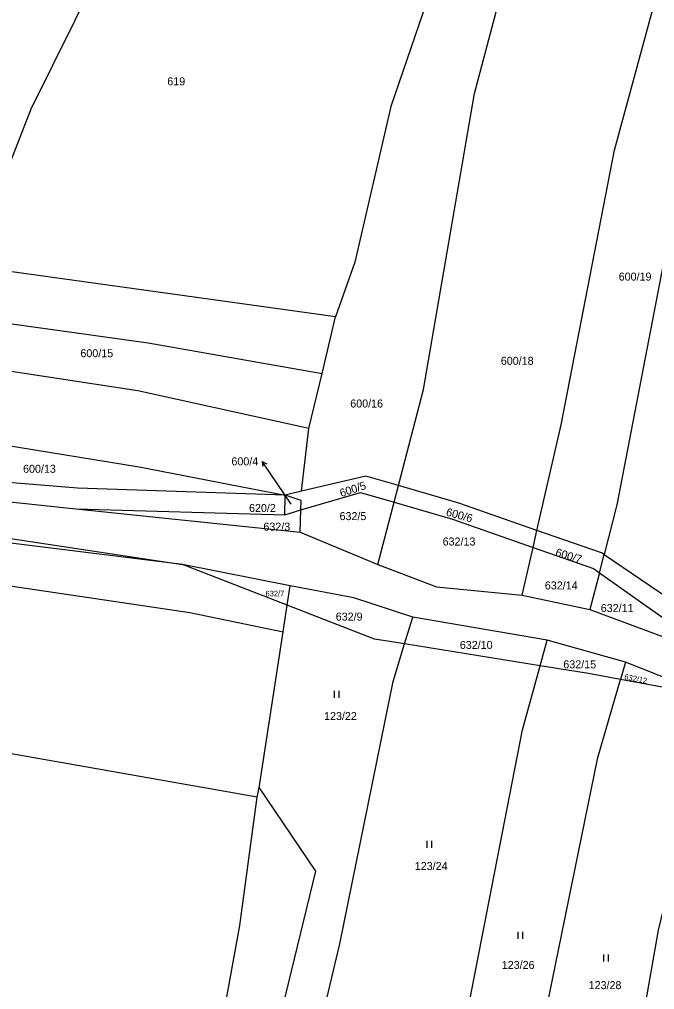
# Model space of a CAD drawing. Extents: x -744566 to -741843, y -1128407 to -1126744.
# Drawn here: x -742633.6 to -742498.8, y -1127345.9 to -1127139.9 of the extents above; entities that cross this region are included whole.
import ezdxf

# ---------------------------------------------------------------- set-up
doc = ezdxf.new("R2010")
doc.units = 0
for name, color, linetype in [('Hranice parcel', 7, 'Continuous'), ('Parcelní čísla', 7, 'Continuous'), ('Pop  PČ popisy', 7, 'Continuous'), ('Značky kultur', 7, 'Continuous')]:
    doc.layers.add(name, color=color, linetype=linetype)

msp = doc.modelspace()

# ---------------------------------------------------------------- linework, layer by layer
at = {"layer": 'Hranice parcel'}
for p, q in [((-742566.48, -1127203.04), (-742644.1, -1127192.22)), ((-742569.32, -1127215.09), (-742566.48, -1127203.04)), ((-742572.17, -1127226.73), (-742569.32, -1127215.09)), ((-742573.72, -1127240.07), (-742572.17, -1127226.73)), ((-742573.72, -1127240.07), (-742577.19, -1127240.89)), ((-742554.07, -1127242.4), (-742553.15, -1127238.87)), ((-742639.2, -1127241.9), (-742621.56, -1127243.8)), ((-742577.26, -1127245.05), (-742577.19, -1127240.89)), ((-742557.53, -1127255.65), (-742554.07, -1127242.4)), ((-742678.76, -1127243.56), (-742598.97, -1127255.65)), ((-742621.56, -1127243.8), (-742574.02, -1127248.78)), ((-742621.56, -1127243.8), (-742577.26, -1127245.05)), ((-742577.26, -1127245.05), (-742573.86, -1127244.05)), ((-742574.02, -1127248.78), (-742573.86, -1127244.05)), ((-742574.02, -1127248.78), (-742557.53, -1127255.65)), ((-742524.58, -1127252.01), (-742523.75, -1127248.38)), ((-742526.9, -1127262.12), (-742524.58, -1127252.01)), ((-742510.5, -1127257.39), (-742509.51, -1127253.53)), ((-742509.51, -1127253.53), (-742483.68, -1127270.99)), ((-742576.08, -1127260.13), (-742598.97, -1127255.65)), ((-742576.72, -1127264.27), (-742598.97, -1127255.65)), ((-742510.5, -1127257.39), (-742512.49, -1127265.17)), ((-742510.5, -1127257.39), (-742484.78, -1127275.57)), ((-742576.72, -1127264.27), (-742576.08, -1127260.13)), ((-742526.9, -1127262.12), (-742512.49, -1127265.17)), ((-742577.59, -1127269.9), (-742576.72, -1127264.27)), ((-742512.49, -1127265.17), (-742484.78, -1127275.57)), ((-742551.83, -1127272.48), (-742550.1, -1127266.78)), ((-742521.55, -1127271.68), (-742550.1, -1127266.78)), ((-742582.72, -1127303.04), (-742577.59, -1127269.9)), ((-742523.05, -1127277.11), (-742551.83, -1127272.48)), ((-742523.05, -1127277.11), (-742521.55, -1127271.68)), ((-742504.98, -1127276.38), (-742521.55, -1127271.68)), ((-742504.98, -1127276.38), (-742506.04, -1127280.03)), ((-742486.41, -1127283.7), (-742504.98, -1127276.38)), ((-742486.41, -1127283.7), (-742506.04, -1127280.03)), ((-742583.12, -1127305.02), (-742582.72, -1127303.04))]:
    msp.add_line(p, q, dxfattribs=at)
for points in [[(-742644.1, -1127192.22), (-742631.06, -1127158.9), (-742603.37, -1127102.87)], [(-742543.65, -1127125.88), (-742554.78, -1127158.4), (-742562.37, -1127191.45), (-742566.48, -1127203.04)], [(-742553.15, -1127238.87), (-742547.82, -1127218.47), (-742536.99, -1127155.61), (-742532.11, -1127137.2)], [(-742523.75, -1127248.38), (-742518.59, -1127225.94), (-742507.29, -1127167.65), (-742498.96, -1127136.92)], [(-742484.3, -1127140.22), (-742493.61, -1127174.67), (-742506.81, -1127242.95), (-742509.51, -1127253.53)], [(-742725.69, -1127194.04), (-742650.94, -1127202.29), (-742606.23, -1127208.56), (-742569.32, -1127215.09)], [(-742572.17, -1127226.73), (-742608.43, -1127218.73), (-742647.39, -1127212.79), (-742690.57, -1127207.86)], [(-742664.96, -1127226.26), (-742655.98, -1127227.12), (-742608.13, -1127234.85), (-742577.19, -1127240.89)], [(-742577.19, -1127240.89), (-742621.26, -1127239.44), (-742638.6, -1127238), (-742659.14, -1127230.44), (-742664.96, -1127226.26)], [(-742553.15, -1127238.87), (-742560.09, -1127236.86), (-742573.72, -1127240.07)], [(-742573.86, -1127244.05), (-742561.22, -1127240.32), (-742554.07, -1127242.4)], [(-742523.75, -1127248.38), (-742540.33, -1127242.59), (-742553.15, -1127238.87)], [(-742573.86, -1127244.05), (-742573.79, -1127242.02), (-742577.19, -1127240.89)], [(-742554.07, -1127242.4), (-742541.7, -1127246.01), (-742524.58, -1127252.01)], [(-742598.97, -1127255.65), (-742642.9, -1127250.2), (-742660.81, -1127251.7), (-742678.76, -1127243.56)], [(-742509.51, -1127253.53), (-742510.08, -1127253.15), (-742523.75, -1127248.38)], [(-742736.14, -1127250.3), (-742715.39, -1127251.55), (-742655.59, -1127257.18), (-742597.39, -1127265.81), (-742577.59, -1127269.9)], [(-742524.58, -1127252.01), (-742511.77, -1127256.49), (-742510.5, -1127257.39)], [(-742557.53, -1127255.65), (-742545.05, -1127260.38), (-742526.9, -1127262.12)], [(-742550.1, -1127266.78), (-742562.63, -1127262.7), (-742576.08, -1127260.13)], [(-742551.83, -1127272.48), (-742558.2, -1127271.45), (-742576.72, -1127264.27)], [(-742571.73, -1127362.05), (-742565.58, -1127336.15), (-742554.25, -1127280.44), (-742551.83, -1127272.48)], [(-742543.19, -1127372.64), (-742538.11, -1127348.86), (-742526.83, -1127290.76), (-742523.05, -1127277.11)], [(-742506.04, -1127280.03), (-742512.81, -1127278.76), (-742523.05, -1127277.11)], [(-742530.91, -1127395.09), (-742510.84, -1127296.63), (-742506.04, -1127280.03)], [(-742583.12, -1127305.02), (-742639.33, -1127295.15), (-742725.03, -1127283.28)], [(-742511.41, -1127409.84), (-742497.94, -1127333.24), (-742489.37, -1127297.91), (-742486.41, -1127283.7)], [(-742582.72, -1127303.04), (-742570.71, -1127320.74), (-742580.44, -1127360.6), (-742571.73, -1127362.05)], [(-742593.77, -1127370.76), (-742586.78, -1127332.31), (-742583.12, -1127305.02)]]:
    msp.add_lwpolyline(points, dxfattribs=at)
at = {"layer": 'Pop  PČ popisy'}
for p, q in [((-742580.36, -1127236.21), (-742582.038, -1127233.722)), ((-742582.038, -1127233.722), (-742581.063, -1127234.272)), ((-742582.038, -1127233.722), (-742581.893, -1127234.832)), ((-742575.92, -1127242.8), (-742580.36, -1127236.21))]:
    msp.add_line(p, q, dxfattribs=at)
at = {"layer": 'Značky kultur'}
for p, q in [((-742566.691, -1127283.93), (-742566.691, -1127282.43)), ((-742565.69, -1127283.93), (-742565.69, -1127282.43)), ((-742547.041, -1127315.8), (-742547.041, -1127314.3)), ((-742546.04, -1127315.8), (-742546.04, -1127314.3)), ((-742527.751, -1127335.11), (-742527.751, -1127333.61)), ((-742526.75, -1127335.11), (-742526.75, -1127333.61)), ((-742509.551, -1127339.91), (-742509.551, -1127338.41)), ((-742508.55, -1127339.91), (-742508.55, -1127338.41))]:
    msp.add_line(p, q, dxfattribs=at)

# ---------------------------------------------------------------- texts
at = {"layer": 'Parcelní čísla'}
for s, height, p in [('619', 1.7, (-742602.18, -1127153.88)), ('600/19', 1.7, (-742506.4, -1127195.34)), ('600/15', 1.7, (-742620.62, -1127211.61)), ('600/18', 1.7, (-742531.41, -1127213.22)), ('600/16', 1.7, (-742563.36, -1127222.29)), ('600/13', 1.7, (-742632.79, -1127236.15)), ('600/4', 1.7, (-742588.576, -1127234.57)), ('620/2', 1.7, (-742584.84, -1127244.48)), ('632/5', 1.7, (-742565.63, -1127246.2)), ('632/3', 1.7, (-742581.79, -1127248.43)), ('632/13', 1.7, (-742543.76, -1127251.59)), ('632/14', 1.7, (-742522.07, -1127260.92)), ('632/7', 1.19, (-742581.35, -1127262.395)), ('632/11', 1.7, (-742510.21, -1127265.72)), ('632/9', 1.7, (-742566.44, -1127267.54)), ('632/10', 1.7, (-742540.11, -1127273.56)), ('632/15', 1.7, (-742518.15, -1127277.67)), ('123/22', 1.7, (-742568.92, -1127288.65)), ('123/24', 1.7, (-742549.67, -1127320.5)), ('123/26', 1.7, (-742531.21, -1127341.5)), ('123/28', 1.7, (-742512.77, -1127345.79))]:
    msp.add_text(s, height=height, dxfattribs=at).set_placement(p)
for s, height, rotation, p in [('600/5', 1.7, 18, (-742565.267, -1127241.328)), ('600/6', 1.7, 345, (-742543.159, -1127245.221)), ('600/7', 1.7, 343, (-742519.968, -1127253.752)), ('632/12', 1.19, 349, (-742505.273, -1127280.004))]:
    msp.add_text(s, height=height, rotation=rotation, dxfattribs=at).set_placement(p)

doc.saveas('drawing.dxf')
